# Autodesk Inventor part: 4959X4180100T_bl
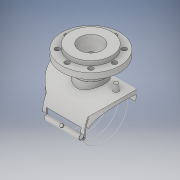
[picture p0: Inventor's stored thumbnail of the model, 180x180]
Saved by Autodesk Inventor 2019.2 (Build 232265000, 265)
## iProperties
Created: 2020-06
Part Number: 4959X4180100T_bl
Material: Generic
Description: Plasson Flanged Branch Saddle 180x100
Document SubType Name: Modeling
Designer: KIM
Density: 1 g/cm^3
Appearance: Default
Author: KIM
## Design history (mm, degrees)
derived "4959X4.ipt"
feature "Solid1::4959X4.ipt" dims "ScaleForDerivedMember" = 10
feature "Solid2::4959X4.ipt" dims "ScaleForDerivedMember" = 10
tag "TaggingFeature1"
body "Solid1"
body "Solid2"
other parameters: "d0" = 263 [user parameter], "d4" = 119 [user parameter], "d7" = 87 [user parameter], "d10" = 0.5 [user parameter], "d11" = 1 [user parameter], "d12" = 29.75 [user parameter], "d13" = 16 [user parameter], "d14" = 8 [user parameter], "d16" = 10 deg [user parameter], "d17" = 10 deg [user parameter], "d19" = 0 [user parameter], "d23" = 0 [user parameter], "d26" = 0 [user parameter], "d27" = 157.8 [user parameter], "d28" = 0 [user parameter], "d29" = 131.5 [user parameter], "d30" = 0 [user parameter], "d31" = 1 [user parameter], "d32" = 1 [user parameter], "d33" = 19.2 [user parameter], "d34" = 9.6 [user parameter], "d35" = 45 deg [user parameter], "d36" = 131.5 [user parameter], "d37" = 0 [user parameter], "d38" = 5 [user parameter], "d39" = 85 deg [user parameter], "d40" = 29.75 [user parameter], "d41" = 16 [user parameter], "d42" = 95.63636 [user parameter], "d49" = 3 [user parameter], "d50" = 6 [user parameter], "d51" = 5 [user parameter], "d54" = 0 [user parameter], "d57" = 35 deg [user parameter], "d60" = 16.4375 [user parameter], "d61" = 1 [user parameter], "d62" = 90 deg [user parameter], "d63" = 2 [user parameter], "d64" = 0 [user parameter], "d65" = 0 [user parameter], "d68" = 32.875 [user parameter], "d70" = 0.57711 [user parameter], "d71" = 10 deg [user parameter], "d73" = 4.9 [user parameter], "d75" = 22 [user parameter], "d77" = 89.25 [user parameter], "d78" = 105 [user parameter], "d79" = 158 [user parameter], "d80" = 1 [user parameter], "d81" = 104.4 [user parameter], "d82" = 121.8 [user parameter], "d83" = 1 [user parameter], "d84" = 16.5 [user parameter], "d87" = 18 [user parameter], "d95" = 360 deg [user parameter], "d_h" = 158 [user parameter], "B" = 229 [user parameter], "L" = 263 [user parameter], "LS" = 105 [user parameter], "H1" = 119 [user parameter], "Dt" = 16 [user parameter], "di" = 87 [user parameter], "s_" = 18 [user parameter], "t" = 22 [user parameter], "d72" = 14 [user parameter]
